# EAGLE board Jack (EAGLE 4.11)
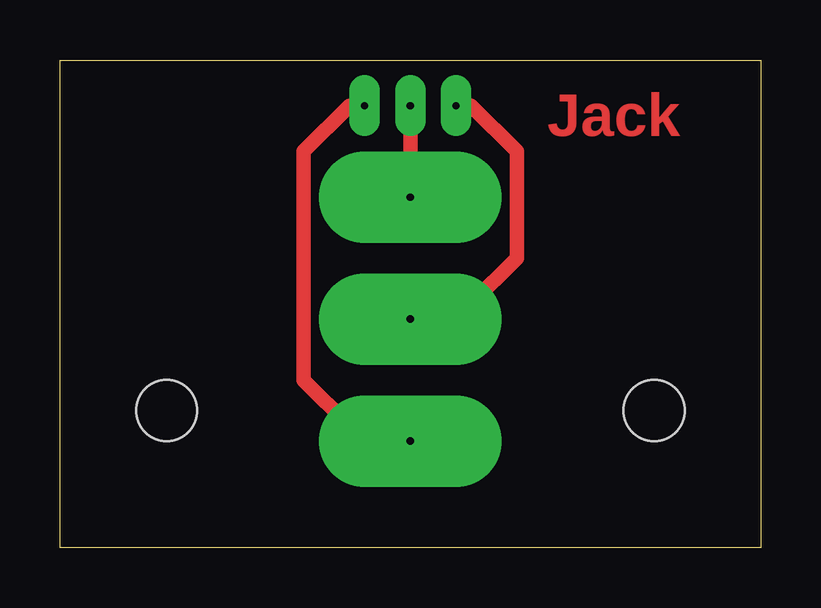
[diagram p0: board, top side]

Size 29.21 x 20.32 mm. Coordinates in mm from the lower left corner, seen from the top.
Outline: 0,0 0,20.32 4.45,20.32 24.77,20.32 29.21,20.32 29.21,0 24.77,0 4.45,0 0,0
Copper layers (1*16): Top 0.035mm / dielectric 1.5mm / Bottom 0.035mm
Design rules "default": minimum track width 10mil, minimum drill 24mil, track to track 8mil, track to pad 8mil, pad to pad 8mil, via to via 8mil, smd to smd 8mil, copper to edge 40mil, drill to drill 8mil, minimum pad ring 10mil, minimum via ring 8mil, stop-mask expansion 4mil, vias tented up to drill 0mil, thermal gap 10mil
Holes 2.54 mm at 4.45,5.71 24.77,5.71

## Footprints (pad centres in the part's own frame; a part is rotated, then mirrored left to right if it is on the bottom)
EC3,81 = drill 0.305 pad 3.81 long: P$1 0,0
EC1,27 = drill 0.305 pad 1.27 long: P$1 0,0

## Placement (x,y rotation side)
E$1  [EC3,81]  14.61,4.45 90 top
E$2  [EC3,81]  14.61,9.53 90 top
E$3  [EC3,81]  14.61,14.61 90 top
E$4  [EC1,27]  14.61,18.41 180 top
E$5  [EC1,27]  16.51,18.41 180 top
E$6  [EC1,27]  12.7,18.41 180 top

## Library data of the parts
E$1-E$6 = Pads

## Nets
S$1: E$3.P$1 E$4.P$1
S$2: E$5.P$1
S$3: E$6.P$1

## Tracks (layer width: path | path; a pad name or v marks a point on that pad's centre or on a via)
S$1
  Top 0.61: E$4.P$1 E$3.P$1
S$2
  Top 0.61: E$5.P$1 17.14,18.41 19.05,16.51 19.05,12.06 17.14,10.16
S$3
  Top 0.61: E$6.P$1 12.06,18.41 10.16,16.51 10.16,6.99 12.06,5.08
S$4  (via drill 0.3)
  other vias: 4.45,5.71
S$5  (via drill 0.3)
  other vias: 24.77,5.71

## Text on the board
Top: Jack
